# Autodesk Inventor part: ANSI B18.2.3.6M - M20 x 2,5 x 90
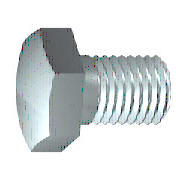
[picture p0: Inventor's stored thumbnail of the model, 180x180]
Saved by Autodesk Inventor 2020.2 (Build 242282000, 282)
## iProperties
Created: 2019-01
Part Number: ANSI B18.2.3.6M - M20 x 2,5 x 90
Material: Stal, miękka
Description: Śruba wzmocniona
Document SubType Name: Modeling
Standard: ANSI B18.2.3.6M
Designer: F.Stasiak
Standard Revision: 2001
Standards Organization: ANSI
Language: pl-PL
Size Designation: M20 x 2,5 x 90
Categories: <MemberInstance><Categories><Category DisplayName="Mocowania" InternalName="e4da775c-781d-43d5-af7c-5136215cf5a6" Mnemonic="FSTN"><Category DisplayName="Śruby"
Density: 7.85 g/cm^3
Appearance: Częściowo polerowany
Manager: www.cadconsulting.pl
Company: Fabian Stasiak CAD Consulting
IsCustomPart: 0
Author: F.Stasiak
Subject: Zbiór ćwiczeń. Autodesk Inventor 2020. Kurs podstawowy
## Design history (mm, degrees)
sketch "Szkic1"
  geometry: L1 (0, 10)-(90, 10); L2 (90, 10)-(90, 0); L3 (90, 0)-(0, 0); L4 (-18, 0)-(108, 0) reference; L5 (0, -2)-(0, 12) reference; L6 (0, 10)-(0, 0)
  constraints: 8 end point, 3 point on line, 1 collinear
  dimensions: "d2" = 20 diameter of L1 L3 (= GD); "d59" = 90 distance between parallel lines of L2 L5 (= NLG)
revolve "Bryła" sketch "Szkic1" stored, may be unused: angle "d12" = 90 deg
sketch "Szkic2"
  geometry: L1 (0, 19.63)-(17, 9.815); L2 (17, 9.815)-(17, -9.815); L3 (17, -9.815)-(0, -19.63); L4 (0, -19.63)-(-17, -9.815); L5 (-17, -9.815)-(-17, 9.815); L6 (-17, 9.815)-(0, 19.63); L7 (-23.8, 0)-(23.8, 0) reference; L8 (0, 27.482)-(0, -27.482) reference; 2 further points
  constraints: 12 end point, 2 midpoint, 1 coincident, 1 vertical, 11 other
  dimensions: "d11" = 34 distance between parallel lines of L5 L2 (= SW)
extrude "Głowica" join sketch "Szkic2" distance "d3" = 13.4 (= KOH); taper "d4" = 0 deg
revolve "Faza1" stored, may be unused: angle "d21" = 90 deg
fillet "Fillet" dims "d71" = 0.8 (= RR1)
workplane "Work Plane1"
body "Solid1"
feature "Gwint" dims "d15" = 46 (= GEL), "d16" = 0
chamfer "Faza2" distance "d6" = 1.53363 (= -0.5 x SPD + 0.5 x GD); stored, may be unused: second distance "d7" = 1.53373 (computed from GUL), angle "d55" = 45 deg
sketch "Szkic4"
  geometry: L1 (-11.437, 20.4)-(-13.4, 17); L2 (-1.1, 0)-(-0.234, 0); L3 (-16.033, 0)-(2.399, 0) reference; L4 (-13.4, 20.4)-(-11.437, 20.4); L5 (-13.4, 17)-(-13.4, 20.4); L6 (0, 24.48)-(0, -4.08) reference
  constraints: 8 end point, 1 parallel, 1 perpendicular, 1 point on line
  dimensions: "d65" = 34 diameter of L1.end L2 (= SW); "d67" = 30 deg angle of L1 L5 (= ANG1); "d68" = 40.8 diameter of L4 L2 (= 1.2 x SW); "d69" = 13.4 distance between parallel lines of L5 L6 (= KOH)
other parameters: "NLG" = 90 [user parameter; used in 1 equation term], "GD" = 20 (= NND) [user parameter; used in 2 equation terms], "KOH" = 13.4 [user parameter; used in 2 equation terms], "GEL" = 46 [user parameter; used in 1 equation term], "SW" = 34 [user parameter; used in 5 equation terms], "SW0" = 34 (= SW) [user parameter], "SPD" = 16.93275 (= NND - 1.2269 x PTC) [user parameter; used in 1 equation term], "SD" = 0 [user parameter], "ANG1" = 30 deg [user parameter; used in 1 equation term], "GAL" = 1.53363 (= 0.61345 x PTC) [user parameter], "GUL" = 1.53363 (= 0.61345 x PTC) [user parameter; used in 1 equation term], "d8" = 0, "RR" = 0.1 [user parameter], "d58" = 0, "RR1" = 0.8 [user parameter; used in 1 equation term], "d73" = 0, "TPU" = 4 (computed from PTC) [user parameter], "GD1" = 16.93275 (= THREADDIA - 1.2269 x PTC) [user parameter], "TOA" = 30 deg [user parameter], "PTC" = 2.5 [user parameter; used in 5 equation terms], "KOH1" = 8.8 [user parameter], "E0" = 39.27 (= 1.155 x SW) [user parameter]
